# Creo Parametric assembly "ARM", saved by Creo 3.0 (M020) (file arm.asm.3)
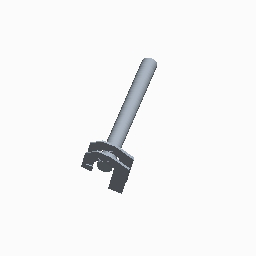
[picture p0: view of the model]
Units: millimeter Newton Second (mmNs); MM, TONNE, SECS

Created from: MMNS_ASM_DESIGN.ASM

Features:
  1. datum plane "ASM_RIGHT"
  2. datum plane "ASM_TOP"
  3. datum plane "ASM_FRONT"
  4. coordinate system
  5. component "PIPE"
  6. component "ARM_MOTOR"
  7. component "ARM_SIDE"
  8. component "ARM_SIDE"
  9. component "ARM_WHEEL2"

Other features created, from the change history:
  component "ARM_MOTOR.PRT"
  component "PIPE.PRT" (2 times)
  sketch "Sketch 1"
